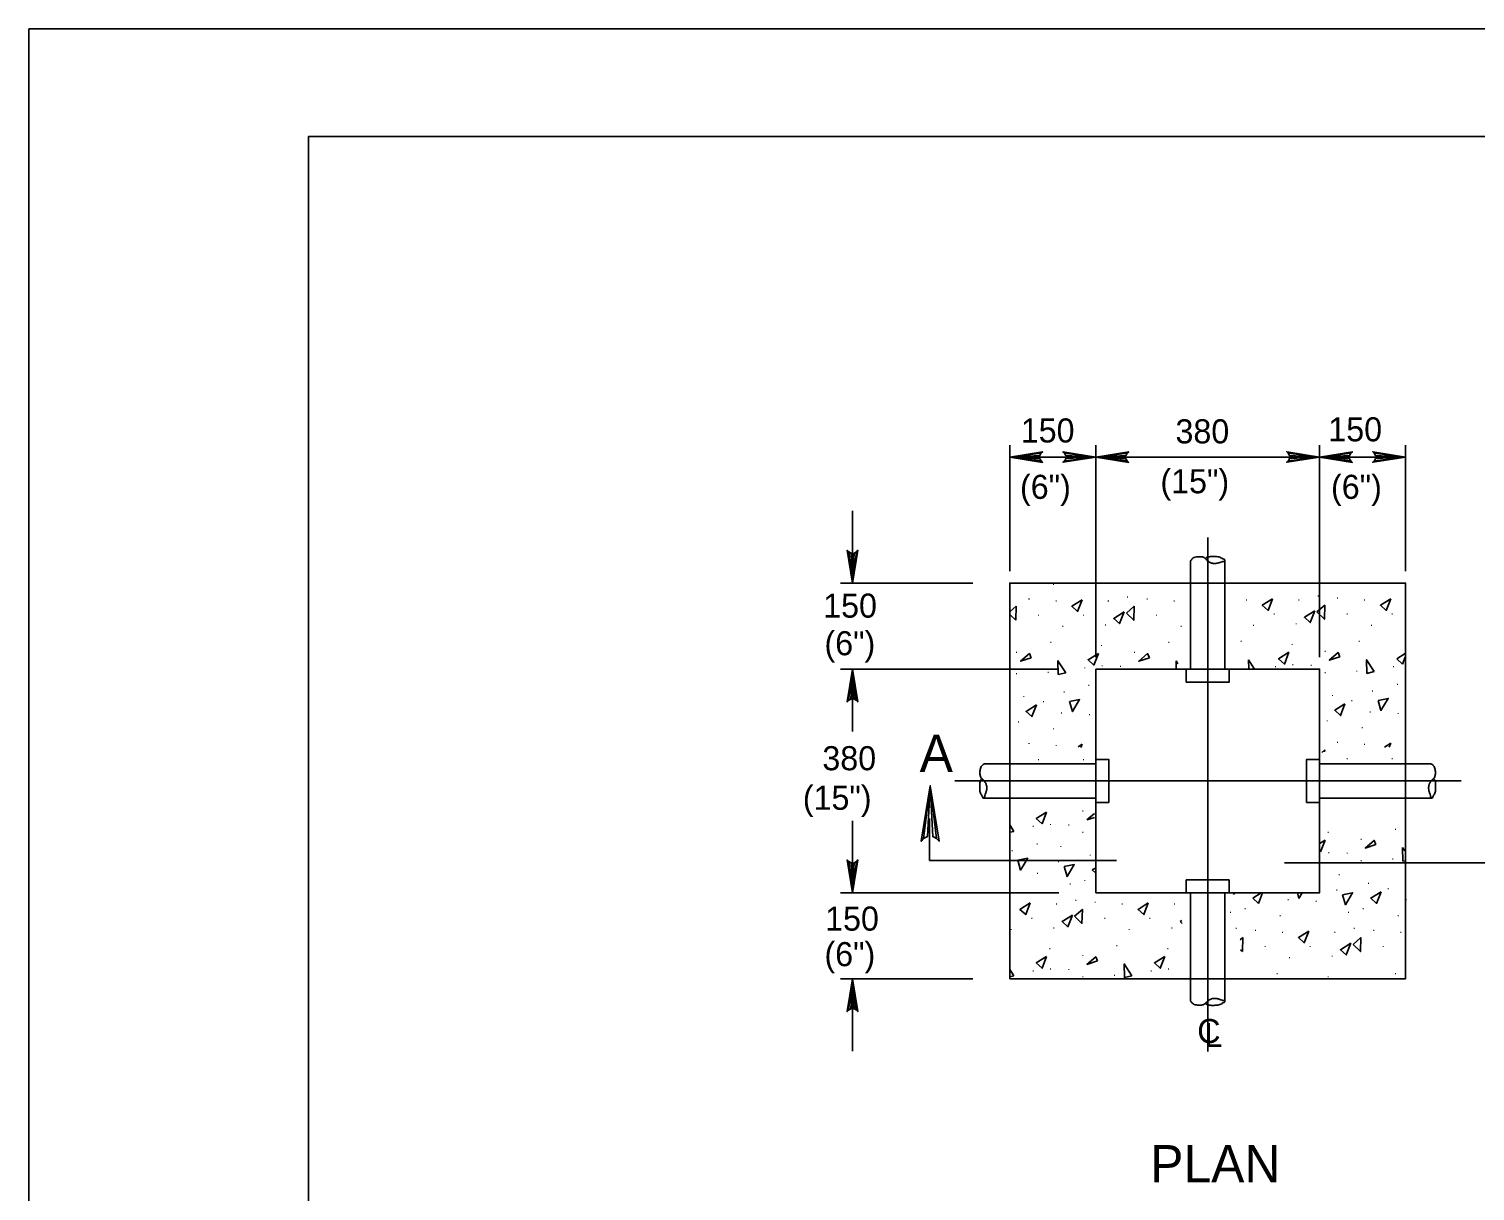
# Model space of a CAD drawing. Extents: x 638447 to 639352, y 298406 to 299000.
# Drawn here: x 638447.4 to 638649.1, y 298838.3 to 299000.5 of the extents above; entities that cross this region are included whole.
import ezdxf

# ---------------------------------------------------------------- set-up
doc = ezdxf.new("R2010")
doc.units = 0
for name, color, linetype in [('1', 7, 'Continuous'), ('2', 7, 'Continuous'), ('3', 7, 'Continuous'), ('PLT-BNDY', 7, 'Continuous')]:
    doc.layers.add(name, color=color, linetype=linetype)

msp = doc.modelspace()

# ---------------------------------------------------------------- linework, layer by layer
at = {"layer": '1'}
msp.add_lwpolyline([(639272.394625, 298421.4725), (639272.394625, 298985.4725), (638486.394625, 298985.4725), (638486.394625, 298421.4725), (639272.394625, 298421.4725), (639272.394625, 298447.8315), (639072.394625, 298447.8315), (639072.394625, 298512.509), (639272.394625, 298512.509), (639272.394625, 298541.4725), (639072.394625, 298541.4725), (639072.394625, 298421.4725), (639151.196125, 298421.4725), (639151.196125, 298447.8315), (639151.196125, 298421.4725), (639228.196125, 298421.4725), (639228.196125, 298447.8315), (639228.196125, 298435.515), (639272.394625, 298435.515)], dxfattribs=at)
at = {"layer": '2'}
for p, q in [((638584.202375, 298924.834), (638584.202375, 298942.422)), ((638596.202375, 298912.834), (638596.202375, 298942.422)), ((638627.402375, 298912.834), (638627.402375, 298942.422)), ((638639.402375, 298924.834), (638639.402375, 298942.422)), ((638584.202375, 298940.742), (638596.202375, 298940.742)), ((638596.202375, 298940.742), (638627.402375, 298940.742)), ((638627.402375, 298940.742), (638639.402375, 298940.742)), ((638562.264125, 298923.154), (638562.264125, 298933.234)), ((638611.802375, 298929.498), (638611.802375, 298857.824)), ((638609.402375, 298926.216), (638609.402375, 298923.154)), ((638614.202375, 298926.3), (638614.202375, 298923.154)), ((638579.034125, 298923.154), (638560.584125, 298923.154)), ((638584.202375, 298923.154), (638584.202375, 298923.154)), ((638609.402375, 298923.154), (638609.402375, 298911.154)), ((638614.202375, 298923.154), (638614.202375, 298911.154)), ((638591.034125, 298911.154), (638560.584125, 298911.154)), ((638562.264125, 298902.43975), (638562.264125, 298911.154)), ((638611.802375, 298911.154), (638611.802375, 298911.154)), ((638580.660375, 298897.954), (638584.202375, 298897.954)), ((638584.202375, 298897.954), (638596.202375, 298897.954)), ((638639.402375, 298897.954), (638627.402375, 298897.954)), ((638642.942375, 298897.954), (638639.402375, 298897.954)), ((638576.514375, 298895.554), (638647.160375, 298895.554)), ((638596.202375, 298895.554), (638596.202375, 298895.554)), ((638627.402375, 298895.554), (638627.402375, 298895.554)), ((638580.578375, 298893.154), (638584.202375, 298893.154)), ((638584.202375, 298893.154), (638596.202375, 298893.154)), ((638639.402375, 298893.154), (638627.402375, 298893.154)), ((638643.024375, 298893.154), (638639.402375, 298893.154)), ((638562.264125, 298889.97175), (638562.264125, 298879.954)), ((638573.004625, 298884.437), (638573.004625, 298890.325)), ((638573.004625, 298884.437), (638599.078625, 298884.437)), ((638622.499875, 298884.136), (638650.724375, 298884.136)), ((638591.034125, 298879.954), (638560.584125, 298879.954)), ((638609.402375, 298879.954), (638609.402375, 298867.954)), ((638611.802375, 298879.954), (638611.802375, 298879.954)), ((638611.802375, 298879.954), (638611.802375, 298879.954)), ((638614.202375, 298879.954), (638614.202375, 298867.954)), ((638579.034125, 298867.954), (638560.584125, 298867.954)), ((638562.264125, 298857.874), (638562.264125, 298867.954)), ((638609.402375, 298867.954), (638609.402375, 298864.894)), ((638614.202375, 298867.954), (638614.202375, 298864.894))]:
    msp.add_line(p, q, dxfattribs=at)
for points in [[(638588.560375, 298940.194), (638588.398375, 298940.51), (638584.202375, 298940.742), (638588.560375, 298940.194), (638588.784375, 298940.004), (638584.202375, 298940.742), (638588.394375, 298940.95), (638588.548375, 298941.262), (638584.202375, 298940.742), (638588.784375, 298941.47), (638588.548375, 298941.262)], [(638591.842375, 298941.29), (638592.004375, 298940.974), (638596.202375, 298940.742), (638591.842375, 298941.29), (638591.618375, 298941.48), (638596.202375, 298940.742), (638592.008375, 298940.534), (638591.854375, 298940.222), (638596.202375, 298940.742), (638591.618375, 298940.014), (638591.854375, 298940.222)], [(638600.560375, 298940.194), (638600.398375, 298940.51), (638596.202375, 298940.742), (638600.560375, 298940.194), (638600.784375, 298940.004), (638596.202375, 298940.742), (638600.394375, 298940.95), (638600.548375, 298941.262), (638596.202375, 298940.742), (638600.784375, 298941.47), (638600.548375, 298941.262)], [(638623.042375, 298941.29), (638623.204375, 298940.974), (638627.402375, 298940.742), (638623.042375, 298941.29), (638622.818375, 298941.48), (638627.402375, 298940.742), (638623.208375, 298940.534), (638623.054375, 298940.222), (638627.402375, 298940.742), (638622.818375, 298940.014), (638623.054375, 298940.222)], [(638631.760375, 298940.194), (638631.598375, 298940.51), (638627.402375, 298940.742), (638631.760375, 298940.194), (638631.984375, 298940.004), (638627.402375, 298940.742), (638631.594375, 298940.95), (638631.748375, 298941.262), (638627.402375, 298940.742), (638631.984375, 298941.47), (638631.748375, 298941.262)], [(638635.042375, 298941.29), (638635.204375, 298940.974), (638639.402375, 298940.742), (638635.042375, 298941.29), (638634.818375, 298941.48), (638639.402375, 298940.742), (638635.208375, 298940.534), (638635.054375, 298940.222), (638639.402375, 298940.742), (638634.818375, 298940.014), (638635.054375, 298940.222)], [(638562.812125, 298927.514), (638562.496125, 298927.352), (638562.264125, 298923.154), (638562.812125, 298927.514), (638563.002125, 298927.738), (638562.264125, 298923.154), (638562.056125, 298927.348), (638561.744125, 298927.502), (638562.264125, 298923.154), (638561.536125, 298927.738), (638561.744125, 298927.502)], [(638584.240375, 298919.19), (638585.076375, 298919.916)], [(638585.076375, 298919.916), (638585.028375, 298917.972)], [(638585.028375, 298917.972), (638584.244375, 298918.74)], [(638639.344375, 298913.34), (638638.164375, 298912.602)], [(638638.980375, 298911.87), (638639.342375, 298912.814)], [(638561.716125, 298906.796), (638562.032125, 298906.958), (638562.264125, 298911.154), (638561.716125, 298906.796), (638561.526125, 298906.572), (638562.264125, 298911.154), (638562.472125, 298906.962), (638562.784125, 298906.808), (638562.264125, 298911.154), (638562.992125, 298906.572), (638562.784125, 298906.808)], [(638596.202375, 298911.154), (638596.202375, 298879.954), (638627.402375, 298879.954), (638627.402375, 298911.154), (638596.202375, 298911.154)], [(638607.406375, 298911.168), (638607.384375, 298912.32)], [(638607.384375, 298912.32), (638607.654375, 298911.904)], [(638617.526375, 298911.154), (638617.500375, 298912.47)], [(638617.500375, 298912.47), (638618.352375, 298911.154)], [(638638.164375, 298912.602), (638638.980375, 298911.87)], [(638637.324375, 298900.818), (638636.440375, 298900.266)], [(638637.110375, 298900.258), (638637.324375, 298900.818)], [(638594.280375, 298900.668), (638593.740375, 298900.33)], [(638594.114375, 298900.23), (638594.280375, 298900.668)], [(638627.702375, 298899.544), (638628.120375, 298899.906)], [(638628.120375, 298899.906), (638628.114375, 298899.626)], [(638572.185625, 298887.51575), (638572.719375, 298887.78975), (638573.108125, 298894.88425), (638572.185625, 298887.51575), (638571.861125, 298887.1375), (638573.108125, 298894.88425), (638573.459875, 298887.79675), (638573.986875, 298887.53625), (638573.108125, 298894.88425), (638574.338625, 298887.1375), (638573.986875, 298887.53625)], [(638589.338375, 298891.222), (638587.898375, 298890.322)], [(638588.714375, 298889.59), (638589.338375, 298891.222)], [(638596.014375, 298891.032), (638594.954375, 298890.118)], [(638584.202375, 298889.414), (638584.778375, 298888.522)], [(638587.898375, 298890.322), (638588.714375, 298889.59)], [(638594.954375, 298890.118), (638596.024375, 298890.47)], [(638584.778375, 298888.522), (638584.202375, 298888.388)], [(638628.170375, 298887.29), (638627.484375, 298886.862)], [(638627.546375, 298885.658), (638628.170375, 298887.29)], [(638627.470375, 298885.724), (638627.546375, 298885.658)], [(638639.030375, 298884.35), (638638.994375, 298886.258)], [(638638.994375, 298886.258), (638639.300375, 298885.784)], [(638562.812125, 298884.314), (638562.496125, 298884.152), (638562.264125, 298879.954), (638562.812125, 298884.314), (638563.002125, 298884.538), (638562.264125, 298879.954), (638562.056125, 298884.148), (638561.744125, 298884.302), (638562.264125, 298879.954), (638561.536125, 298884.538), (638561.744125, 298884.302)], [(638596.142375, 298883.402), (638595.710375, 298883.134)], [(638595.710375, 298883.134), (638596.154375, 298882.736)], [(638639.308375, 298884.414), (638639.030375, 298884.35)], [(638615.362375, 298879.92), (638615.442375, 298879.934)], [(638615.544375, 298879.934), (638615.406375, 298879.706)], [(638619.260375, 298879.942), (638618.078375, 298879.202)], [(638618.078375, 298879.202), (638618.894375, 298878.47)], [(638618.894375, 298878.47), (638619.456375, 298879.942)], [(638624.534375, 298879.178), (638624.314375, 298879.95)], [(638625.000375, 298879.95), (638624.534375, 298879.178)], [(638608.180375, 298876.088), (638607.950375, 298875.946)], [(638607.950375, 298875.946), (638608.248375, 298875.678)], [(638616.342375, 298873.396), (638616.686375, 298873.694)], [(638616.686375, 298873.694), (638616.638375, 298871.75)], [(638616.638375, 298871.75), (638616.390375, 298871.992)], [(638584.202375, 298869.254), (638584.778375, 298868.362)], [(638561.716125, 298863.596), (638562.032125, 298863.758), (638562.264125, 298867.954), (638561.716125, 298863.596), (638561.526125, 298863.372), (638562.264125, 298867.954), (638562.472125, 298863.762), (638562.784125, 298863.608), (638562.264125, 298867.954), (638562.992125, 298863.372), (638562.784125, 298863.608)], [(638584.778375, 298868.362), (638584.202375, 298868.228)]]:
    msp.add_lwpolyline(points, dxfattribs=at)
for points in [[(638584.202375, 298867.954), (638584.202375, 298923.154), (638639.402375, 298923.154), (638639.402375, 298867.954)], [(638620.860375, 298920.978), (638619.420375, 298920.078), (638620.236375, 298919.346)], [(638637.324375, 298920.978), (638635.884375, 298920.078), (638636.700375, 298919.346)], [(638594.280375, 298920.828), (638592.840375, 298919.928), (638593.656375, 298919.196)], [(638600.148375, 298919.136), (638598.708375, 298918.236), (638599.524375, 298917.504)], [(638600.460375, 298918.98), (638601.540375, 298919.916), (638601.492375, 298917.972)], [(638626.728375, 298919.286), (638625.288375, 298918.386), (638626.104375, 298917.654)], [(638627.040375, 298919.13), (638628.120375, 298920.066), (638628.072375, 298918.122)], [(638587.200375, 298912.74), (638586.948375, 298913.316), (638585.712375, 298912.248)], [(638596.560375, 298913.352), (638595.120375, 298912.452), (638595.936375, 298911.72)], [(638603.664375, 298912.74), (638603.412375, 298913.316), (638602.176375, 298912.248)], [(638623.140375, 298913.502), (638621.700375, 298912.602), (638622.516375, 298911.87)], [(638630.244375, 298912.89), (638629.992375, 298913.466), (638628.756375, 298912.398)], [(638592.000375, 298910.652), (638590.956375, 298910.412), (638590.920375, 298912.32)], [(638614.802375, 298911.154), (638608.802375, 298911.154), (638608.802375, 298909.354), (638614.802375, 298909.354)], [(638635.044375, 298910.802), (638634.000375, 298910.562), (638633.964375, 298912.47)], [(638592.528375, 298906.632), (638593.932375, 298906.908), (638592.924375, 298905.24)], [(638635.572375, 298906.782), (638636.976375, 298907.058), (638635.968375, 298905.39)], [(638587.908375, 298906.164), (638586.468375, 298905.264), (638587.284375, 298904.532)], [(638630.952375, 298906.314), (638629.512375, 298905.414), (638630.328375, 298904.682)], [(638598.002375, 298892.554), (638598.002375, 298898.554), (638596.202375, 298898.554), (638596.202375, 298892.554)], [(638627.402375, 298892.554), (638627.402375, 298898.554), (638625.602375, 298898.554), (638625.602375, 298892.554)], [(638635.274375, 298886.678), (638635.022375, 298887.254), (638633.786375, 298886.186)], [(638585.306375, 298884.502), (638586.710375, 298884.778), (638585.702375, 298883.11)], [(638591.786375, 298883.614), (638593.190375, 298883.89), (638592.182375, 298882.222)], [(638614.802375, 298881.754), (638608.802375, 298881.754), (638608.802375, 298879.954), (638614.802375, 298879.954)], [(638587.058375, 298878.538), (638585.618375, 298877.638), (638586.434375, 298876.906)], [(638603.522375, 298878.538), (638602.082375, 298877.638), (638602.898375, 298876.906)], [(638630.618375, 298879.682), (638632.022375, 298879.958), (638631.014375, 298878.29)], [(638635.982375, 298880.102), (638634.542375, 298879.202), (638635.358375, 298878.47)], [(638592.926375, 298876.846), (638591.486375, 298875.946), (638592.302375, 298875.214)], [(638593.238375, 298876.69), (638594.318375, 298877.626), (638594.270375, 298875.682)], [(638625.890375, 298874.606), (638624.450375, 298873.706), (638625.266375, 298872.974)], [(638631.758375, 298872.914), (638630.318375, 298872.014), (638631.134375, 298871.282)], [(638632.070375, 298872.758), (638633.150375, 298873.694), (638633.102375, 298871.75)], [(638589.338375, 298871.062), (638587.898375, 298870.162), (638588.714375, 298869.43)], [(638596.442375, 298870.45), (638596.190375, 298871.026), (638594.954375, 298869.958)], [(638605.802375, 298871.062), (638604.362375, 298870.162), (638605.178375, 298869.43)], [(638601.242375, 298868.362), (638600.198375, 298868.122), (638600.162375, 298870.03)]]:
    msp.add_lwpolyline(points, close=True, dxfattribs=at)
for points in [[(638609.402375, 298926.216), (638609.676375, 298926.576), (638610.218375, 298926.804), (638610.792375, 298926.836), (638611.300375, 298926.716), (638611.658375, 298926.402), (638611.938375, 298926.164), (638612.328375, 298925.948), (638612.836375, 298925.894), (638613.074375, 298925.916), (638613.496375, 298926.034), (638613.822375, 298926.144), (638614.190375, 298926.294), (638614.202375, 298926.392)], [(638614.202375, 298926.392), (638614.136375, 298926.436), (638613.930375, 298926.532), (638613.756375, 298926.63), (638613.486375, 298926.76), (638613.238375, 298926.836), (638612.826375, 298926.858), (638612.544375, 298926.868), (638612.306375, 298926.868), (638612.068375, 298926.836), (638611.798375, 298926.804), (638611.646375, 298926.706), (638611.484375, 298926.566)], [(638580.660375, 298897.954), (638580.300375, 298897.68), (638580.074375, 298897.138), (638580.042375, 298896.564), (638580.160375, 298896.056), (638580.474375, 298895.698), (638580.712375, 298895.418), (638580.928375, 298895.028), (638580.982375, 298894.52), (638580.962375, 298894.282), (638580.842375, 298893.86), (638580.734375, 298893.534), (638580.582375, 298893.166), (638580.486375, 298893.154)], [(638642.942375, 298897.954), (638643.302375, 298897.68), (638643.528375, 298897.138), (638643.562375, 298896.564), (638643.442375, 298896.056), (638643.128375, 298895.698), (638642.890375, 298895.418), (638642.674375, 298895.028), (638642.620375, 298894.52), (638642.642375, 298894.282), (638642.760375, 298893.86), (638642.868375, 298893.534), (638643.020375, 298893.166), (638643.118375, 298893.154)], [(638580.486375, 298893.154), (638580.442375, 298893.22), (638580.344375, 298893.426), (638580.246375, 298893.6), (638580.118375, 298893.87), (638580.042375, 298894.118), (638580.020375, 298894.53), (638580.008375, 298894.812), (638580.008375, 298895.05), (638580.042375, 298895.288), (638580.074375, 298895.558), (638580.172375, 298895.71), (638580.312375, 298895.872)], [(638643.118375, 298893.154), (638643.160375, 298893.22), (638643.258375, 298893.426), (638643.356375, 298893.6), (638643.486375, 298893.87), (638643.562375, 298894.118), (638643.582375, 298894.53), (638643.594375, 298894.812), (638643.594375, 298895.05), (638643.562375, 298895.288), (638643.528375, 298895.558), (638643.432375, 298895.71), (638643.290375, 298895.872)], [(638609.402375, 298864.894), (638609.676375, 298864.534), (638610.218375, 298864.306), (638610.792375, 298864.274), (638611.300375, 298864.394), (638611.658375, 298864.706), (638611.938375, 298864.946), (638612.328375, 298865.162), (638612.836375, 298865.216), (638613.074375, 298865.194), (638613.496375, 298865.074), (638613.822375, 298864.966), (638614.190375, 298864.816), (638614.202375, 298864.718)], [(638614.202375, 298864.718), (638614.136375, 298864.674), (638613.930375, 298864.578), (638613.756375, 298864.48), (638613.486375, 298864.35), (638613.238375, 298864.274), (638612.826375, 298864.252), (638612.544375, 298864.242), (638612.306375, 298864.242), (638612.068375, 298864.274), (638611.798375, 298864.306), (638611.646375, 298864.404), (638611.484375, 298864.544)]]:
    msp.add_spline(points, degree=3, dxfattribs=at)
at = {"layer": 'PLT-BNDY'}
msp.add_lwpolyline([(638447.394625, 299000.4725), (639288.394625, 299000.4725), (639288.394625, 298406.4725), (638447.394625, 298406.4725)], close=True, dxfattribs=at)

# ---------------------------------------------------------------- texts
at = {"layer": '1'}
for s, p in [('(15")', (638605.207875, 298935.6875)), ('(6")', (638585.625625, 298934.90825)), ('(6")', (638629.003625, 298934.90825)), ('(6")', (638558.352125, 298913.08925)), ('(15")', (638555.336375, 298891.53025)), ('(6")', (638558.352125, 298869.7115))]:
    msp.add_text(s, height=3.36, dxfattribs=at).set_placement(p)
at = {"layer": '2'}
for p in [(638590.080375, 298922.904), (638616.660375, 298923.054), (638633.124375, 298923.054), (638586.672375, 298920.852), (638600.412375, 298921.116), (638603.136375, 298920.852), (638617.020375, 298920.726), (638624.316375, 298920.726), (638626.992375, 298921.266), (638629.716375, 298921.002), (638633.484375, 298920.726), (638590.440375, 298920.576), (638597.736375, 298920.576), (638606.904375, 298920.576), (638620.860375, 298918.746), (638631.036375, 298918.746), (638637.324375, 298918.746), (638587.992375, 298918.596), (638591.412375, 298917.036), (638594.280375, 298918.596), (638597.352375, 298917.24), (638604.456375, 298918.596), (638607.876375, 298917.036), (638617.992375, 298917.186), (638623.932375, 298917.39), (638634.456375, 298917.186), (638589.696375, 298914.792), (638606.160375, 298914.792), (638616.276375, 298914.942), (638632.740375, 298914.942), (638584.932375, 298913.4), (638596.800375, 298914.36), (638601.396375, 298913.4), (638623.380375, 298914.51), (638627.976375, 298913.55), (638589.336375, 298910.628), (638594.472375, 298911.252), (638596.884375, 298911.528), (638599.428375, 298911.456), (638621.052375, 298911.402), (638623.464375, 298911.678), (638626.008375, 298911.606), (638632.380375, 298910.778), (638637.516375, 298911.402), (638584.932375, 298910.424), (638595.012375, 298908.804), (638627.976375, 298910.574), (638638.056375, 298908.954), (638585.964375, 298907.244), (638591.556375, 298907.868), (638629.008375, 298907.394), (638631.720375, 298906.662), (638634.600375, 298908.018), (638588.676375, 298906.512), (638591.220375, 298904.952), (638595.096375, 298904.724), (638634.264375, 298905.102), (638638.140375, 298904.874), (638585.196375, 298903.704), (638590.080375, 298902.744), (638628.240375, 298903.854), (638633.124375, 298902.894), (638586.672375, 298900.692), (638629.716375, 298900.842), (638633.484375, 298900.566), (638590.440375, 298900.416), (638631.036375, 298898.586), (638637.324375, 298898.586), (638587.992375, 298898.436), (638594.280375, 298898.436)]:
    msp.add_text('.', height=1.116, dxfattribs=at).set_placement(p)
at = {"layer": '3'}
for s, height, p in [('150', 3.36, (638585.732125, 298942.772)), ('380', 3.36, (638607.310625, 298942.648)), ('150', 3.36, (638628.628375, 298942.93125)), ('150', 3.36, (638558.174125, 298918.3355)), ('A', 5.2, (638571.628375, 298896.8155)), ('380', 3.36, (638558.060375, 298897.04725)), ('.', 1.116, (638594.174375, 298891.27)), ('.', 1.116, (638587.250375, 298889.122)), ('.', 1.116, (638589.662375, 298889.398)), ('.', 1.116, (638592.206375, 298889.326)), ('.', 1.116, (638637.770375, 298888.73)), ('.', 1.116, (638587.790375, 298886.674)), ('.', 1.116, (638594.174375, 298888.294)), ('.', 1.116, (638628.410375, 298888.298)), ('.', 1.116, (638633.006375, 298887.338)), ('.', 1.116, (638584.334375, 298885.738)), ('.', 1.116, (638591.090375, 298886.326)), ('.', 1.116, (638595.206375, 298885.114)), ('.', 1.116, (638628.494375, 298885.466)), ('.', 1.116, (638631.038375, 298885.394)), ('.', 1.116, (638637.410375, 298884.566)), ('.', 1.116, (638587.874375, 298882.594)), ('.', 1.116, (638590.778375, 298884.19)), ('.', 1.116, (638590.778375, 298884.19)), ('.', 1.116, (638629.922375, 298882.394)), ('.', 1.116, (638633.006375, 298884.362)), ('.', 1.116, (638592.410375, 298881.082)), ('.', 1.116, (638594.438375, 298881.574)), ('.', 1.116, (638634.038375, 298881.182)), ('.', 1.116, (638636.750375, 298880.45)), ('.', 1.116, (638593.190375, 298878.826)), ('.', 1.116, (638595.914375, 298878.562)), ('.', 1.116, (638622.830375, 298878.89)), ('.', 1.116, (638626.706375, 298878.662)), ('.', 1.116, (638629.610375, 298880.258)), ('.', 1.116, (638629.610375, 298880.258)), ('.', 1.116, (638639.294375, 298878.89)), ('150', 3.36, (638558.445625, 298874.66975)), ('.', 1.116, (638590.514375, 298878.286)), ('.', 1.116, (638599.682375, 298878.286)), ('.', 1.116, (638606.978375, 298878.286)), ('.', 1.116, (638614.778375, 298877.15)), ('.', 1.116, (638616.806375, 298877.642)), ('.', 1.116, (638621.690375, 298876.682)), ('.', 1.116, (638631.242375, 298877.15)), ('.', 1.116, (638633.270375, 298877.642)), ('.', 1.116, (638638.154375, 298876.682)), ('.', 1.116, (638584.190375, 298874.746)), ('.', 1.116, (638587.058375, 298876.306)), ('.', 1.116, (638590.130375, 298874.95)), ('.', 1.116, (638597.234375, 298876.306)), ('.', 1.116, (638600.654375, 298874.746)), ('.', 1.116, (638603.522375, 298876.306)), ('.', 1.116, (638606.594375, 298874.95)), ('.', 1.116, (638615.558375, 298874.894)), ('.', 1.116, (638618.282375, 298874.63)), ('.', 1.116, (638622.050375, 298874.354)), ('.', 1.116, (638629.346375, 298874.354)), ('.', 1.116, (638632.022375, 298874.894)), ('.', 1.116, (638634.746375, 298874.63)), ('.', 1.116, (638638.514375, 298874.354)), ('.', 1.116, (638598.938375, 298872.502)), ('.', 1.116, (638619.602375, 298872.374)), ('.', 1.116, (638625.890375, 298872.374)), ('.', 1.116, (638636.066375, 298872.374)), ('.', 1.116, (638589.578375, 298872.07)), ('.', 1.116, (638594.174375, 298871.11)), ('.', 1.116, (638606.042375, 298872.07)), ('.', 1.116, (638623.022375, 298870.814)), ('.', 1.116, (638628.962375, 298871.018)), ('.', 1.116, (638587.250375, 298868.962)), ('.', 1.116, (638589.662375, 298869.238)), ('.', 1.116, (638592.206375, 298869.166)), ('.', 1.116, (638598.578375, 298868.338)), ('.', 1.116, (638603.714375, 298868.962)), ('.', 1.116, (638606.126375, 298869.238)), ('.', 1.116, (638621.306375, 298868.57)), ('.', 1.116, (638637.770375, 298868.57)), ('.', 1.116, (638594.174375, 298868.134)), ('.', 1.116, (638628.410375, 298868.138)), ('C', 3.359988, (638610.344375, 298858.988)), ('L', 3.359988, (638611.340375, 298858.416)), ('PLAN', 5.2000005, (638603.780875, 298839.55))]:
    msp.add_text(s, height=height, dxfattribs=at).set_placement(p)

doc.saveas('drawing.dxf')
